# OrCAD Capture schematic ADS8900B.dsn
size A
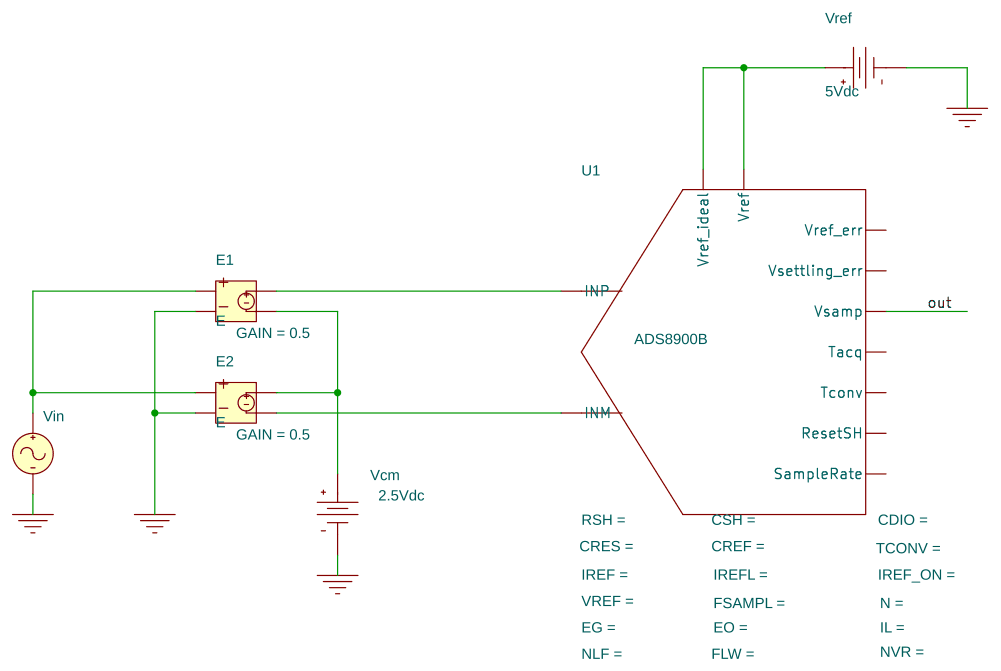
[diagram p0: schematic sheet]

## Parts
E1  E
E2  E
U1  ADS8900B
Vcm  VDC
Vin  VAC
Vref  VDC

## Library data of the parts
E1 E2 = E: GAIN: 0.5
U1 = ADS8900B
Vcm = VDC: DC: 2.5Vdc
Vin = VAC
Vref = VDC: DC: 5Vdc

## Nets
0: E1.2 E2.2 Vcm.1(-) Vin.2(-) Vref.1(-)
out: U1.Vsamp
N16344: U1.Vref U1.Vref_ideal Vref.0(+)
N16520: E1.1 E2.1 Vin.1(+)
N16530: E1.3 U1.INP
N16546: E1.4 E2.3 Vcm.0(+)
N16616: E2.4 U1.INM

Not connected (* = marked no-connect by the designer): U1 ResetSH SampleRate Tacq Tconv Vref_err Vsettling_err
